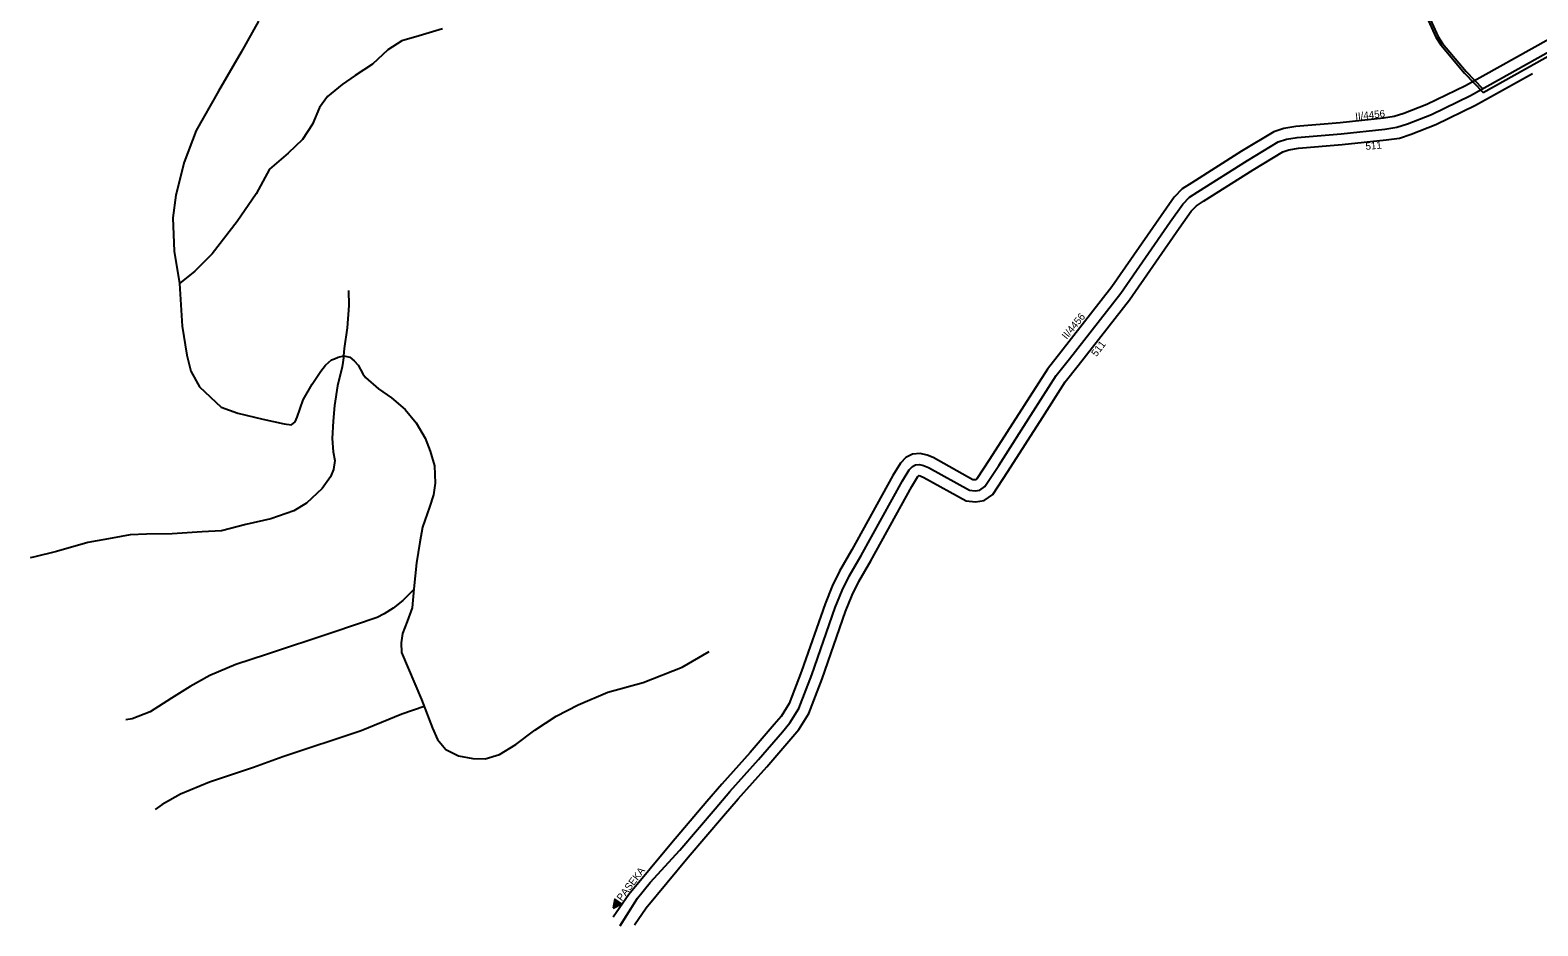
# Model space of a CAD drawing. Extents: x -547395 to -536032, y -1096268 to -1086572.
# Drawn here: x -547395 to -545330, y -1096093 to -1094866 of the extents above; entities that cross this region are included whole.
import ezdxf

# ---------------------------------------------------------------- set-up
doc = ezdxf.new("R2010")
doc.units = 0
for name, color, linetype in [('Vrstva 12', 7, 'Continuous'), ('Vrstva 66', 7, 'Continuous'), ('Vrstva 7', 7, 'Continuous'), ('Vrstva 70', 7, 'Continuous'), ('Vrstva 73', 7, 'Continuous')]:
    doc.layers.add(name, color=color, linetype=linetype)

msp = doc.modelspace()

# ---------------------------------------------------------------- linework, layer by layer
at = {"layer": 'Vrstva 12'}
for points in [[(-547082.6, -1094853.1), (-547106.4, -1094895.9), (-547137.3, -1094949.4), (-547167.9, -1095003.1), (-547184.2, -1095046.7), (-547195.8, -1095091.6), (-547199.9, -1095122.9), (-547197.8, -1095168.5), (-547190.7, -1095213), (-547186.9, -1095271.6), (-547180.7, -1095311.1), (-547175.3, -1095332.9), (-547163.1, -1095354.6), (-547133.8, -1095382.6), (-547110.7, -1095390.7), (-547076.7, -1095398.9), (-547047.3, -1095405.2), (-547037.1, -1095406.5), (-547032.4, -1095402.5), (-547029.6, -1095396.3), (-547021.5, -1095372.5), (-547009.2, -1095350.7), (-546997, -1095333.1), (-546990.9, -1095324.9), (-546982.6, -1095317.7), (-546978.6, -1095316), (-546973.2, -1095314), (-546965.7, -1095312), (-546957.6, -1095314), (-546951.3, -1095319.1), (-546946, -1095324.9), (-546939.6, -1095336.6), (-546935.8, -1095341.9), (-546918.1, -1095357.5), (-546900.5, -1095369.8), (-546881.4, -1095385.4), (-546866.5, -1095403.8), (-546854.2, -1095424.9), (-546847.4, -1095442.6), (-546841.3, -1095463), (-546840.6, -1095486.8), (-546842.7, -1095502.5), (-546848.1, -1095519.5), (-546858, -1095547.1), (-546861.4, -1095567.5), (-546866.1, -1095596), (-546869.5, -1095631.4), (-546872.2, -1095657.3), (-546879, -1095676.3), (-546885.2, -1095692.7), (-546887.2, -1095705.6), (-546886.5, -1095718.5), (-546859.3, -1095783.2), (-546844, -1095822.3), (-546837.2, -1095837.9), (-546825.7, -1095851.5), (-546808.7, -1095860.4), (-546789, -1095863.8), (-546772, -1095864.5), (-546752.2, -1095858.4), (-546729.8, -1095844.7), (-546704, -1095825), (-546674.7, -1095805.9), (-546644.8, -1095790.3), (-546604, -1095773.3), (-546555.4, -1095760), (-546502.1, -1095738.6), (-546465.3, -1095717.5)], [(-545481.1, -1094842.5), (-545466.9, -1094873.8), (-545460.6, -1094883.9), (-545428.1, -1094922.5), (-545405.5, -1094945.7)], [(-546830.3, -1094864), (-546862.3, -1094873.5), (-546886.1, -1094880.3), (-546905.1, -1094892.6), (-546926.2, -1094912.3), (-546950, -1094927.9), (-546967.7, -1094940.2), (-546988.1, -1094956.5), (-546999, -1094971.5), (-547008.5, -1094994.6), (-547022.1, -1095015.7), (-547041.8, -1095034.1), (-547067.3, -1095056.2), (-547085.6, -1095090.2), (-547111.8, -1095128), (-547145.8, -1095172.2), (-547169.6, -1095196), (-547190.7, -1095213)], [(-546965.7, -1095312), (-546964.9, -1095302.1), (-546960.5, -1095273.5), (-546958.1, -1095242.9), (-546958.8, -1095222.5)], [(-546965.7, -1095312), (-546967.8, -1095327.3), (-546974.2, -1095353.1), (-546978.3, -1095380.3), (-546980.3, -1095401.4), (-546981.5, -1095425.4), (-546980.2, -1095443.8), (-546978.1, -1095455.4), (-546979.8, -1095467.9), (-546983.9, -1095477.8), (-546995.1, -1095493.8), (-547016.9, -1095513.9), (-547034.2, -1095524.4), (-547065.5, -1095535.3), (-547099.7, -1095543.3), (-547133, -1095551.8), (-547159.5, -1095553.5), (-547200.6, -1095555.9), (-547236, -1095556.6), (-547258.4, -1095557.2), (-547282.9, -1095562), (-547316.2, -1095568.1), (-547359, -1095580.4), (-547390.8, -1095588), (-547395.3, -1095588.8)], [(-546869.6, -1095632.3), (-546884.7, -1095647.2), (-546897.9, -1095658.1), (-546910.5, -1095665.6), (-546920, -1095670.7), (-546980.8, -1095691.5), (-547071.6, -1095721.4), (-547113.4, -1095735), (-547149.1, -1095750.3), (-547176.2, -1095765.1), (-547201.7, -1095781.1), (-547230.7, -1095800), (-547255.5, -1095809.5), (-547264.3, -1095811.2)], [(-546855.6, -1095792.6), (-546886, -1095803.4), (-546941.8, -1095825.9), (-547049.2, -1095861.9), (-547089.3, -1095876.2), (-547149.8, -1095896.6), (-547189.2, -1095912.9), (-547214.4, -1095927.2), (-547224, -1095933.8)]]:
    msp.add_lwpolyline(points, dxfattribs=at)
at = {"layer": 'Vrstva 66'}
for points in [[(-545314.4, -1094877.8), (-545429.2, -1094941.8), (-545481.8, -1094967.5), (-545513.6, -1094979.9), (-545526.6, -1094984.2), (-545541.5, -1094986.5), (-545600.7, -1094992.7), (-545661.5, -1094997.8), (-545677.7, -1095000.4), (-545691.8, -1095004.8), (-545735.7, -1095031.4), (-545803.9, -1095074.7), (-545817, -1095083), (-545827.9, -1095094.7), (-545845.8, -1095120), (-545913.4, -1095217.3), (-545983.2, -1095306.8), (-546001.8, -1095330.2), (-546033.8, -1095380.3), (-546081, -1095454.3), (-546098.3, -1095480.6), (-546100.1, -1095481.9), (-546101.3, -1095482.1), (-546103.8, -1095481.8), (-546158.2, -1095451.6), (-546166.6, -1095448.2), (-546176.2, -1095445.7), (-546186.4, -1095446.9), (-546195.7, -1095451.3), (-546203.2, -1095459.3), (-546213.4, -1095476), (-546269.9, -1095578.2), (-546286.8, -1095607.2), (-546296.8, -1095627.8), (-546306.3, -1095651.8), (-546338.6, -1095744.3), (-546355.6, -1095788.8), (-546366.7, -1095806.4), (-546376.1, -1095817.6), (-546408.8, -1095855.6), (-546447.9, -1095899.4), (-546468.1, -1095923), (-546516.6, -1095979.9), (-546575.2, -1096050.6), (-546596.8, -1096081.7)], [(-546567.3, -1096091.9), (-546551.3, -1096068.7), (-546493.7, -1095999.2), (-546445.3, -1095942.5), (-546425.3, -1095919.1), (-546386.2, -1095875.4), (-546353.3, -1095837), (-546342.4, -1095824.2), (-546328.6, -1095802.3), (-546310.4, -1095754.6), (-546278.2, -1095662.3), (-546269.3, -1095639.9), (-546260.3, -1095621.3), (-546243.8, -1095593), (-546187.4, -1095491.1), (-546179.2, -1095477.5), (-546178, -1095476.2), (-546175.9, -1095476.7), (-546171.2, -1095478.7), (-546113.2, -1095510.9), (-546100.3, -1095512.4), (-546088.4, -1095510.2), (-546076.5, -1095502), (-546055.8, -1095470.6), (-546008.5, -1095396.4), (-545977.4, -1095347.7), (-545959.7, -1095325.3), (-545889.2, -1095235.1), (-545821.2, -1095137.2), (-545804.6, -1095113.7), (-545797.7, -1095106.3), (-545787.8, -1095100), (-545719.9, -1095057), (-545679.3, -1095032.4), (-545670.8, -1095029.7), (-545657.9, -1095027.6), (-545597.9, -1095022.5), (-545537.7, -1095016.2), (-545519.6, -1095013.5), (-545503.4, -1095008.2), (-545469.8, -1094995), (-545415.3, -1094968.4), (-545337.4, -1094925)]]:
    msp.add_lwpolyline(points, dxfattribs=at)
at = {"layer": 'Vrstva 7'}
msp.add_lwpolyline([(-546587, -1096093.1), (-546563.2, -1096055.3), (-546546.1, -1096034.1), (-546505.2, -1095989.5), (-546456.7, -1095932.8), (-546436.6, -1095909.2), (-546397.5, -1095865.5), (-546364.7, -1095827.3), (-546354.6, -1095815.3), (-546342.1, -1095795.6), (-546324.5, -1095749.5), (-546292.3, -1095657.1), (-546283.1, -1095633.9), (-546273.5, -1095614.2), (-546256.9, -1095585.6), (-546200.4, -1095483.6), (-546191.2, -1095468.4), (-546186.7, -1095463.6), (-546182.3, -1095461.6), (-546177.2, -1095461), (-546171.3, -1095462.4), (-546164.7, -1095465.1), (-546108.5, -1095496.4), (-546100.8, -1095497.3), (-546094.2, -1095496.1), (-546087.4, -1095491.3), (-546068.4, -1095462.4), (-546021.1, -1095388.4), (-545989.6, -1095338.9), (-545971.4, -1095316), (-545901.3, -1095226.2), (-545833.5, -1095128.6), (-545816.2, -1095104.2), (-545807.3, -1095094.6), (-545795.9, -1095087.4), (-545727.8, -1095044.2), (-545685.6, -1095018.6), (-545674.3, -1095015), (-545659.7, -1095012.7), (-545599.3, -1095007.6), (-545539.6, -1095001.4), (-545523.1, -1094998.8), (-545508.5, -1094994.1), (-545475.8, -1094981.3), (-545422.3, -1094955.1), (-545306.9, -1094890.8)], dxfattribs=at)
for points in [[(-546596.8, -1096069.3), (-546585.4, -1096063.4), (-546594.3, -1096056.7)], [(-546595.7, -1096067.8), (-546586.9, -1096063.3), (-546593.7, -1096058.1)], [(-546594.6, -1096066.3), (-546588.4, -1096063.2), (-546593.2, -1096059.5)], [(-546593.5, -1096064.9), (-546589.9, -1096063), (-546592.7, -1096060.9)], [(-546592.4, -1096063.4), (-546591.4, -1096062.9), (-546592.2, -1096062.3)]]:
    msp.add_lwpolyline(points, close=True, dxfattribs=at)
at = {"layer": 'Vrstva 70'}
for points in [[(-545483.8, -1094843.8), (-545469.5, -1094875.2), (-545463, -1094885.7), (-545430.3, -1094924.5), (-545404.6, -1094950.9)], [(-545404.6, -1094950.9), (-545304.4, -1094895.1)]]:
    msp.add_lwpolyline(points, dxfattribs=at)
at = {"layer": 'Vrstva 73'}
msp.add_lwpolyline([(-546587.2, -1096093.4), (-546563.2, -1096055.3), (-546546.1, -1096034.1), (-546505.2, -1095989.5), (-546456.7, -1095932.8), (-546436.6, -1095909.2), (-546397.5, -1095865.5), (-546364.7, -1095827.3), (-546354.6, -1095815.3), (-546342.1, -1095795.6), (-546324.5, -1095749.5), (-546292.3, -1095657.1), (-546283.1, -1095633.9), (-546273.5, -1095614.2), (-546256.9, -1095585.6), (-546200.4, -1095483.6), (-546191.2, -1095468.4), (-546186.7, -1095463.6), (-546182.3, -1095461.6), (-546177.2, -1095461), (-546171.3, -1095462.4), (-546164.7, -1095465.1), (-546108.5, -1095496.4), (-546100.8, -1095497.3), (-546094.2, -1095496.1), (-546087.4, -1095491.3), (-546068.4, -1095462.4), (-546021.1, -1095388.4), (-545989.6, -1095338.9), (-545971.4, -1095316), (-545901.3, -1095226.2), (-545833.5, -1095128.6), (-545816.2, -1095104.2), (-545807.3, -1095094.6), (-545795.9, -1095087.4), (-545727.8, -1095044.2), (-545685.6, -1095018.6), (-545674.3, -1095015), (-545659.7, -1095012.7), (-545599.3, -1095007.6), (-545539.6, -1095001.4), (-545523.1, -1094998.8), (-545508.5, -1094994.1), (-545475.8, -1094981.3), (-545422.3, -1094955.1), (-545306.9, -1094890.8)], dxfattribs=at)

# ---------------------------------------------------------------- texts
at = {"layer": 'Vrstva 7'}
for s, rotation, p in [('II/4456', 5.9696, (-545579.5, -1094988.9)), ('II/4456', 50.5199, (-545975.3, -1095290.2)), ('PASEKA', 52.7379, (-546584.8, -1096060.3))]:
    msp.add_text(s, height=10, rotation=rotation, dxfattribs=at).set_placement(p)
at = {"layer": 'Vrstva 73'}
for rotation, p in [(4.7885, (-545565.6, -1095029.8)), (52.2925, (-545934.7, -1095314))]:
    msp.add_text('511', height=10, rotation=rotation, dxfattribs=at).set_placement(p)

doc.saveas('drawing.dxf')
